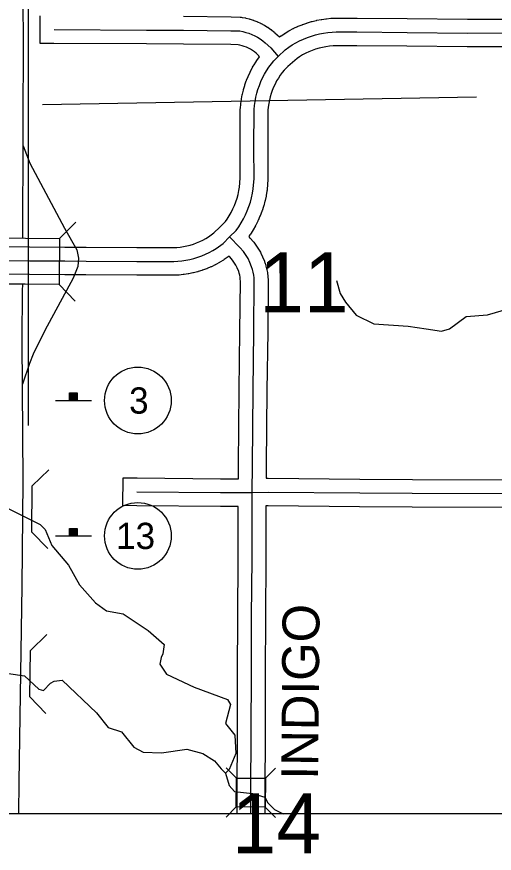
# Model space of a CAD drawing. Extents: x -2251611 to -2054719, y -2227156 to -2099355.
# Drawn here: x -2135345 to -2129880, y -2144765 to -2135199 of the extents above; entities that cross this region are included whole.
import ezdxf

# ---------------------------------------------------------------- set-up
doc = ezdxf.new("R2010")
doc.units = 0
for name, color, linetype in [('Default', 7, 'Continuous'), ('dsnTextFinalPlan', 7, 'Continuous'), ('dsnTextNote', 7, 'Continuous'), ('Level 35', 7, 'Continuous'), ('tdCoHydroRiver', 7, 'Continuous'), ('tdCoInt', 7, 'Continuous'), ('tdCoIntRamp', 7, 'Continuous'), ('tdCoSecRdTxt', 7, 'Continuous'), ('tdCoSecRteBand', 7, 'Continuous'), ('tdCoSectLinePart', 7, 'Continuous'), ('tdCoSectNmbr', 7, 'Continuous'), ('tdCoStrucDivPri', 7, 'Continuous'), ('tdCoStrucNonDivPri', 7, 'Continuous'), ('tdCoStrucSec', 7, 'Continuous'), ('tdCoSurfAsphalt', 7, 'Continuous'), ('tdCoSurfConc', 7, 'Continuous'), ('tdCoSurfEarth', 7, 'Continuous'), ('tdCoSurfGravel', 7, 'Continuous')]:
    doc.layers.add(name, color=color, linetype=linetype)

msp = doc.modelspace()

# ---------------------------------------------------------------- linework, layer by layer
at = {"layer": 'Default'}
msp.add_line((-2135211.4, -2139873.6), (-2135211.4, -2130143.9), dxfattribs=at)
at = {"layer": 'dsnTextFinalPlan'}
for p, q in [((-2134901.9, -2139587.8), (-2134489.4, -2139587.8)), ((-2134738.9, -2139507.9), (-2134655.1, -2139507.9)), ((-2134655.1, -2139512.7), (-2134738.9, -2139512.7)), ((-2134738.9, -2139516), (-2134655.1, -2139516)), ((-2134655.1, -2139520.8), (-2134738.9, -2139520.8)), ((-2134738.9, -2139524.2), (-2134655.1, -2139523.9)), ((-2134655.1, -2139530.4), (-2134738.9, -2139530.7)), ((-2134738.9, -2139533.7), (-2134655.1, -2139533.7)), ((-2134655.1, -2139540.2), (-2134738.9, -2139540.2)), ((-2134738.9, -2139545.8), (-2134655.1, -2139545.8)), ((-2134655.1, -2139550.6), (-2134738.9, -2139550.9)), ((-2134738.9, -2139554), (-2134655.1, -2139554)), ((-2134655.1, -2139557.9), (-2134738.9, -2139557.9)), ((-2134738.9, -2139563), (-2134655.1, -2139563)), ((-2134655.1, -2139566.1), (-2134738.9, -2139566.1)), ((-2134738.9, -2139569.5), (-2134655.1, -2139569.5)), ((-2134655.1, -2139573.4), (-2134738.9, -2139573.4)), ((-2134738.9, -2139577.3), (-2134655.1, -2139577.3)), ((-2134655.1, -2139581.6), (-2134738.9, -2139581.6)), ((-2134738.9, -2141056.2), (-2134655.1, -2141056.2)), ((-2134655.1, -2141061), (-2134738.9, -2141061)), ((-2134738.9, -2141064.4), (-2134655.1, -2141064.4)), ((-2134655.1, -2141069.2), (-2134738.9, -2141069.2)), ((-2134738.9, -2141072.5), (-2134655.1, -2141072.3)), ((-2134655.1, -2141078.7), (-2134738.9, -2141079)), ((-2134738.9, -2141082.1), (-2134655.1, -2141082.1)), ((-2134655.1, -2141088.6), (-2134738.9, -2141088.6)), ((-2134738.9, -2141094.2), (-2134655.1, -2141094.2)), ((-2134655.1, -2141099), (-2134738.9, -2141099.3)), ((-2134738.9, -2141102.4), (-2134655.1, -2141102.4)), ((-2134655.1, -2141106.3), (-2134738.9, -2141106.3)), ((-2134738.9, -2141111.4), (-2134655.1, -2141111.4)), ((-2134655.1, -2141114.4), (-2134738.9, -2141114.4)), ((-2134738.9, -2141117.8), (-2134655.1, -2141117.8)), ((-2134655.1, -2141121.8), (-2134738.9, -2141121.8)), ((-2134738.9, -2141125.7), (-2134655.1, -2141125.7)), ((-2134901.9, -2141136.1), (-2134489.4, -2141136.1)), ((-2134655.1, -2141129.9), (-2134738.9, -2141129.9))]:
    msp.add_line(p, q, dxfattribs=at)
for points in [[(-2134655.1, -2139586.3), (-2134739.5, -2139586.3), (-2134739.5, -2139502), (-2134655.1, -2139502)], [(-2134655.1, -2141134.7), (-2134739.5, -2141134.7), (-2134739.5, -2141050.3), (-2134655.1, -2141050.3)]]:
    msp.add_lwpolyline(points, close=True, dxfattribs=at)
at = {"layer": 'dsnTextNote'}
msp.add_lwpolyline([(-2138305.1, -2118109.7), (-2124095.9, -2118109.7), (-2124095.9, -2144315.9), (-2146959.9, -2144315.9), (-2146959.9, -2118109.7), (-2138305.1, -2118109.7)], dxfattribs=at)
for centre in [(-2133958.9, -2139587.8), (-2133958.9, -2141136.1)]:
    msp.add_circle(centre, 381.4, dxfattribs=at)
at = {"layer": 'Level 35'}
msp.add_lwpolyline([(-2136026.4, -2137722.3), (-2134855.8, -2137734.1), (-2134861.1, -2138261.9), (-2136033.1, -2138251.9)], close=True, dxfattribs=at)
at = {"layer": 'tdCoHydroRiver'}
for points in [[(-2131685.2, -2138213.7), (-2131643.2, -2138363.6), (-2131584.6, -2138463.5), (-2131459.3, -2138613.1), (-2131259.1, -2138712.7), (-2130867.4, -2138736.8), (-2130659, -2138769.6), (-2130483.9, -2138794.2), (-2130392.3, -2138769), (-2130201, -2138626.9), (-2129959.4, -2138609.7), (-2129709.6, -2138534.1)], [(-2135729.1, -2140681.2), (-2135078.4, -2141004.6), (-2135019.9, -2141062.8), (-2134944.5, -2141246), (-2134752.3, -2141470.5), (-2134626.8, -2141695.2), (-2134443, -2141903.1), (-2134317.8, -2141994.4), (-2134126, -2142027.3), (-2133842.3, -2142218.3), (-2133658.6, -2142376.2), (-2133675, -2142484.6), (-2133691.6, -2142526.3), (-2133708.1, -2142601.3), (-2133632.8, -2142717.8), (-2133315.8, -2142867), (-2132932.2, -2143007.8), (-2132898.7, -2143066), (-2132956.5, -2143282.8), (-2132847.9, -2143415.9), (-2132839.1, -2143624.2), (-2132913.6, -2143807.6), (-2132955.2, -2143849.4)], [(-2135807.8, -2142656.2), (-2135257.6, -2142738.2), (-2135090.6, -2142887.8), (-2135040.6, -2142904.3), (-2134957.4, -2142820.8), (-2134915.8, -2142795.7), (-2134824.2, -2142787.2), (-2134431.7, -2143161.2), (-2134298, -2143327.6), (-2134147.9, -2143377.2), (-2134005.8, -2143551.9), (-2133897.4, -2143610), (-2133689, -2143617.8), (-2133397.5, -2143575.5), (-2133214, -2143625.1), (-2133080.5, -2143708.1), (-2133005.3, -2143799.5), (-2132955.2, -2143849.4)], [(-2132955.2, -2143849.4), (-2132913.2, -2143991), (-2132854.7, -2144057.5), (-2132646.4, -2144082), (-2132504.6, -2144123.4), (-2132471.1, -2144189.9), (-2132396, -2144264.8), (-2132296, -2144315.9)]]:
    msp.add_lwpolyline(points, dxfattribs=at)
at = {"layer": 'tdCoInt'}
for points in [[(-2135275.9, -2137726.7), (-2135266.4, -2135362.5), (-2135283.2, -2134507.8), (-2135280.8, -2130380.1), (-2135260.2, -2129703.7), (-2135216.9, -2129339.5), (-2135162.2, -2129034.2), (-2135027.4, -2128516.2), (-2134871.9, -2128070.7), (-2134130.5, -2126105.6), (-2133742.1, -2125075.1), (-2133739, -2125066.2)], [(-2135322.6, -2144315.9), (-2135318.4, -2143949.7), (-2135284.3, -2141709.3), (-2135271.9, -2140509.2), (-2135282.8, -2138906), (-2135277.3, -2138327.8)], [(-2135277.4, -2138329.8), (-2135275.9, -2138261.1)]]:
    msp.add_lwpolyline(points, dxfattribs=at)
at = {"layer": 'tdCoIntRamp'}
msp.add_lwpolyline([(-2135271.7, -2136677.3), (-2135194, -2136874.8), (-2134798.4, -2137617), (-2134656.8, -2137864.4), (-2134637.7, -2137959), (-2134645.3, -2138055.3), (-2134697.5, -2138188.3), (-2135024.7, -2138788.9), (-2135156.5, -2139059.1), (-2135200.5, -2139166.5), (-2135279.4, -2139400.4)], dxfattribs=at)
at = {"layer": 'tdCoSecRteBand'}
for points in [[(-2133970.4, -2137839.2), (-2133551.9, -2137839.2), (-2133513.2, -2137837.2), (-2133474.4, -2137833.3), (-2133435.9, -2137827.4), (-2133397.8, -2137819.7), (-2133360.1, -2137810.1), (-2133322.8, -2137798.6), (-2133286.3, -2137785.3), (-2133250.4, -2137770.2), (-2133215.3, -2137753.4), (-2133181, -2137734.8), (-2133149.7, -2137715.8), (-2133089.2, -2137672.1), (-2133020.3, -2137604.9), (-2132956.9, -2137542), (-2132937, -2137513.8), (-2132913.1, -2137476.2), (-2132891.2, -2137437.5), (-2132871.2, -2137397.7), (-2132853.2, -2137357), (-2132837.2, -2137315.5), (-2132823.3, -2137273.2), (-2132811.5, -2137230.2), (-2132801.9, -2137186.8), (-2132795.1, -2137146.9), (-2132788.2, -2137044.6), (-2132789.5, -2136700), (-2132789.5, -2136699.2), (-2132789.5, -2136698.5), (-2132786.9, -2136259.7), (-2132786.9, -2136252.8), (-2132786.2, -2136246), (-2132781.9, -2136199), (-2132781.5, -2136195.2), (-2132781, -2136191.4), (-2132774.4, -2136144.7), (-2132773.8, -2136140.9), (-2132773.1, -2136137.1), (-2132764.2, -2136090.8), (-2132763.4, -2136087), (-2132762.5, -2136083.2), (-2132751.4, -2136037.4), (-2132750.5, -2136033.6), (-2132749.4, -2136029.9), (-2132736, -2135984.7), (-2132734.9, -2135981), (-2132733.6, -2135977.4), (-2132718, -2135932.9), (-2132716.8, -2135929.2), (-2132715.3, -2135925.6), (-2132697.6, -2135881.9), (-2132696.1, -2135878.3), (-2132694.5, -2135874.8), (-2132674.7, -2135832.1), (-2132673, -2135828.6), (-2132671.2, -2135825.1), (-2132649.3, -2135783.4), (-2132647.6, -2135779.9), (-2132645.6, -2135776.6), (-2132621.7, -2135736), (-2132619.7, -2135732.6), (-2132617.6, -2135729.4), (-2132591.7, -2135690), (-2132589.6, -2135686.7), (-2132587.3, -2135683.6), (-2132568, -2135657), (-2132575.6, -2135649.1), (-2132572.7, -2135646.4), (-2132604.8, -2135615.7), (-2132623.7, -2135600.7), (-2132645.5, -2135585.4), (-2132668.2, -2135571.4), (-2132691.7, -2135558.9), (-2132715.9, -2135547.8), (-2132740.8, -2135538.2), (-2132766.2, -2135530.1), (-2132792, -2135523.6), (-2132810.3, -2135520.1), (-2132896.7, -2135517.9), (-2133437.9, -2135511.4), (-2133859, -2135510.1), (-2133859.2, -2135510.1), (-2133859.3, -2135510.1), (-2134919.2, -2135504.9), (-2135077.6, -2135504.1), (-2135076.1, -2135187.3)], [(-2133434.8, -2135194.6), (-2132891.8, -2135201.1), (-2132890.7, -2135201.2), (-2132889.6, -2135201.2), (-2132789.3, -2135203.8), (-2132776.6, -2135204.1), (-2132764, -2135206.5), (-2132728.4, -2135213.2), (-2132723.7, -2135214.1), (-2132719, -2135215.3), (-2132683.9, -2135224.2), (-2132679.2, -2135225.3), (-2132674.7, -2135226.8), (-2132640.1, -2135237.8), (-2132635.6, -2135239.3), (-2132631.1, -2135241), (-2132597.3, -2135254), (-2132592.8, -2135255.8), (-2132588.4, -2135257.8), (-2132555.5, -2135272.9), (-2132551.1, -2135274.9), (-2132546.9, -2135277.1), (-2132514.9, -2135294.2), (-2132510.7, -2135296.4), (-2132506.6, -2135298.9), (-2132475.7, -2135317.9), (-2132471.6, -2135320.4), (-2132467.6, -2135323.2), (-2132438, -2135344), (-2132434, -2135346.7), (-2132430.3, -2135349.7), (-2132401.9, -2135372.3), (-2132396.2, -2135376.8), (-2132390.9, -2135381.9), (-2132339.9, -2135430.8), (-2132325.6, -2135420.4), (-2132322.5, -2135418.2), (-2132319.3, -2135416.1), (-2132278.9, -2135389.6), (-2132275.6, -2135387.5), (-2132272.3, -2135385.6), (-2132230.7, -2135361.1), (-2132227.3, -2135359.2), (-2132224, -2135357.4), (-2132181.1, -2135335), (-2132177.7, -2135333.2), (-2132174.2, -2135331.6), (-2132130.4, -2135311.3), (-2132126.9, -2135309.7), (-2132123.4, -2135308.2), (-2132078.6, -2135290), (-2132075, -2135288.6), (-2132071.4, -2135287.3), (-2132025.8, -2135271.3), (-2132022.2, -2135270.1), (-2132018.5, -2135269), (-2131972.1, -2135255.2), (-2131968.5, -2135254.1), (-2131964.7, -2135253.2), (-2131917.8, -2135241.7), (-2131914.1, -2135240.8), (-2131910.3, -2135240.1), (-2131862.9, -2135230.9), (-2131859.1, -2135230.1), (-2131855.3, -2135229.6), (-2131807.5, -2135222.7), (-2131803.7, -2135222.1), (-2131799.8, -2135221.8), (-2131751.7, -2135217.2), (-2131747.9, -2135216.8), (-2131744.1, -2135216.6), (-2131695.8, -2135214.4), (-2131692.1, -2135214.2), (-2131688.4, -2135214.2), (-2131451.4, -2135214.2), (-2131450.7, -2135214.2), (-2131450, -2135214.2), (-2130877.1, -2135219.4), (-2130876.9, -2135219.4), (-2130876.7, -2135219.4), (-2130187.6, -2135227.2), (-2129049.3, -2135225.9)], [(-2129049.3, -2135542.7), (-2130188.2, -2135544), (-2130189.2, -2135544), (-2130190.2, -2135544), (-2130880.1, -2135536.2), (-2131452.2, -2135531), (-2131684.7, -2135531), (-2131725.5, -2135532.9), (-2131766, -2135536.8), (-2131806.2, -2135542.6), (-2131846.1, -2135550.3), (-2131885.6, -2135560), (-2131924.6, -2135571.6), (-2131963, -2135585), (-2132000.7, -2135600.3), (-2132037.6, -2135617.4), (-2132073.6, -2135636.3), (-2132108.7, -2135656.9), (-2132137.7, -2135675.9), (-2132244.2, -2135770.1), (-2132285, -2135809.3), (-2132305.8, -2135835.1), (-2132329, -2135867), (-2132350.6, -2135899.9), (-2132370.6, -2135933.9), (-2132388.9, -2135968.8), (-2132405.5, -2136004.6), (-2132420.3, -2136041.1), (-2132433.3, -2136078.3), (-2132444.5, -2136116.1), (-2132453.8, -2136154.4), (-2132461.3, -2136193.1), (-2132466.8, -2136232.1), (-2132470.2, -2136268.4), (-2132472.7, -2136699.6), (-2132471.4, -2137049.1), (-2132471.4, -2137054.7), (-2132471.8, -2137060.3), (-2132479.6, -2137176.2), (-2132480.1, -2137184.2), (-2132481.5, -2137192.1), (-2132490.2, -2137243.7), (-2132490.9, -2137247.6), (-2132491.8, -2137251.5), (-2132503.1, -2137302.6), (-2132503.9, -2137306.4), (-2132505, -2137310.2), (-2132518.8, -2137360.7), (-2132519.9, -2137364.5), (-2132521.1, -2137368.3), (-2132537.4, -2137418), (-2132538.7, -2137421.8), (-2132540.1, -2137425.4), (-2132558.8, -2137474.3), (-2132560.3, -2137478), (-2132561.8, -2137481.6), (-2132583, -2137529.5), (-2132584.6, -2137533.1), (-2132586.4, -2137536.6), (-2132609.9, -2137583.4), (-2132611.7, -2137586.9), (-2132613.6, -2137590.3), (-2132639.5, -2137635.9), (-2132641.4, -2137639.3), (-2132643.5, -2137642.6), (-2132671.6, -2137686.8), (-2132673.7, -2137690.1), (-2132676, -2137693.4), (-2132690.3, -2137713.7), (-2132685.2, -2137718.8), (-2132686.1, -2137719.6), (-2132680, -2137725.9), (-2132678.3, -2137727.6), (-2132676.7, -2137729.4), (-2132632.4, -2137777.5), (-2132623.2, -2137787.5), (-2132615.9, -2137798.9), (-2132563.8, -2137879.6), (-2132556.9, -2137890.3), (-2132551.8, -2137902.1), (-2132532.8, -2137945.5), (-2132511.4, -2137994.5), (-2132508, -2138002.3), (-2132505.5, -2138010.4), (-2132495.7, -2138041.6), (-2132494.2, -2138046.1), (-2132493.1, -2138050.7), (-2132485.2, -2138082.4), (-2132484, -2138087), (-2132483.1, -2138091.7), (-2132477.1, -2138123.9), (-2132476.2, -2138128.5), (-2132475.6, -2138133.2), (-2132471.6, -2138165.7), (-2132471, -2138170.4), (-2132470.7, -2138175.1), (-2132468.6, -2138207.8), (-2132468.2, -2138213.6), (-2132468.2, -2138219.5), (-2132473.4, -2138801.5), (-2132473.4, -2138801.9), (-2132473.4, -2138802.2), (-2132482.6, -2139473.6), (-2132489.1, -2140324.7), (-2132489.1, -2140324.8), (-2132489.1, -2140324.8), (-2132490.3, -2140477), (-2132471.9, -2140476.6), (-2132469.4, -2140476.5), (-2132466.9, -2140476.5), (-2131418.9, -2140485.7), (-2130817.6, -2140489.6), (-2129765.6, -2140494.8)], [(-2135855.2, -2137824.3), (-2135197.4, -2137830.8), (-2134792.8, -2137833.2), (-2134792.6, -2137833.3), (-2134792.5, -2137833.3), (-2134550.6, -2137834.7), (-2134550.4, -2137834.7), (-2134550.3, -2137834.7), (-2133970.4, -2137839.2)], [(-2132823.7, -2144315.9), (-2132822.8, -2144085.9), (-2132822.8, -2144085.8), (-2132822.8, -2144085.7), (-2132818.9, -2143371.1), (-2132817.6, -2142713.8), (-2132817.6, -2142713.7), (-2132817.6, -2142713.5), (-2132815, -2142054.7), (-2132815, -2142054.3), (-2132815, -2142054), (-2132809.8, -2141401), (-2132809.8, -2140799.5), (-2133013.3, -2140798.5), (-2133013.6, -2140798.5), (-2133013.8, -2140798.5), (-2133970.8, -2140790.7), (-2134129.2, -2140789.4), (-2134126.6, -2140472.6), (-2133968.3, -2140473.9), (-2133011.5, -2140481.7), (-2132807.2, -2140482.8), (-2132807.1, -2140479.4), (-2132805.8, -2140322.3), (-2132799.3, -2139470.7), (-2132799.3, -2139470.3), (-2132799.3, -2139469.8), (-2132790.2, -2138798.3), (-2132785.1, -2138222.5), (-2132786.5, -2138200.4), (-2132789.4, -2138177.4), (-2132793.7, -2138154.6), (-2132799.3, -2138132.1), (-2132805.1, -2138113.5), (-2132823.1, -2138072.3), (-2132837, -2138040.6), (-2132874.8, -2137982), (-2132908.3, -2137945.5), (-2132915.9, -2137937.7), (-2132969.4, -2137976.3), (-2132974.5, -2137980), (-2132979.8, -2137983.2), (-2133019.8, -2138007.5), (-2133023.1, -2138009.5), (-2133026.5, -2138011.4), (-2133067.7, -2138033.7), (-2133071.1, -2138035.6), (-2133074.6, -2138037.3), (-2133116.8, -2138057.5), (-2133120.3, -2138059.2), (-2133124, -2138060.7), (-2133167.1, -2138078.9), (-2133170.7, -2138080.4), (-2133174.4, -2138081.7), (-2133218.3, -2138097.7), (-2133222, -2138099), (-2133225.8, -2138100.2), (-2133270.5, -2138114), (-2133274.2, -2138115.1), (-2133278, -2138116.1), (-2133323.3, -2138127.6), (-2133327.1, -2138128.6), (-2133331, -2138129.4), (-2133376.8, -2138138.7), (-2133380.7, -2138139.5), (-2133384.5, -2138140.1), (-2133430.8, -2138147.1), (-2133434.7, -2138147.7), (-2133438.6, -2138148.1), (-2133485.1, -2138152.8), (-2133489, -2138153.2), (-2133492.9, -2138153.4), (-2133539.6, -2138155.8), (-2133543.7, -2138156), (-2133547.8, -2138156), (-2133971, -2138156), (-2133971.6, -2138156), (-2133972.2, -2138156), (-2134552.6, -2138151.5), (-2134794.6, -2138150), (-2134794.9, -2138150), (-2134795, -2138150), (-2135199.6, -2138147.6), (-2135199.9, -2138147.6), (-2135200.2, -2138147.6), (-2135859.1, -2138141.1)], [(-2129767.7, -2140811.6), (-2130819.3, -2140806.3), (-2130819.4, -2140806.3), (-2130819.5, -2140806.3), (-2131421.1, -2140802.4), (-2131421.3, -2140802.4), (-2131421.4, -2140802.4), (-2132467.1, -2140793.3), (-2132488.1, -2140793.8), (-2132492.9, -2140793.9), (-2132493, -2140796.8), (-2132493, -2141401.6), (-2132493, -2141402.3), (-2132493, -2141402.9), (-2132498.2, -2142056.2), (-2132500.8, -2142714.6), (-2132502.1, -2143372), (-2132502.1, -2143372.3), (-2132502.1, -2143372.6), (-2132506, -2144087.3), (-2132506.9, -2144315.9)]]:
    msp.add_lwpolyline(points, dxfattribs=at)
at = {"layer": 'tdCoSectLinePart'}
msp.add_lwpolyline([(-2135051.4, -2136202.8), (-2130082.7, -2136117.1)], dxfattribs=at)
at = {"layer": 'tdCoStrucDivPri'}
for points in [[(-2134987.6, -2141281.1), (-2135172.3, -2141092.5), (-2135166.8, -2140564.5), (-2134978.2, -2140379.8)], [(-2135013.4, -2143166.1), (-2135197, -2142976.4), (-2135188.4, -2142448.5), (-2134998.8, -2142264.9)]]:
    msp.add_lwpolyline(points, dxfattribs=at)
at = {"layer": 'tdCoStrucNonDivPri'}
for p, q in [((-2134855.9, -2137733.9), (-2134667.3, -2137549.1)), ((-2134861.1, -2138261.9), (-2134676.2, -2138450.4))]:
    msp.add_line(p, q, dxfattribs=at)
msp.add_lwpolyline([(-2136026.4, -2137722.3), (-2134855.9, -2137733.9), (-2134861.1, -2138261.9), (-2136031.6, -2138250.3)], close=True, dxfattribs=at)
at = {"layer": 'tdCoStrucSec'}
for p, q in [((-2132830.5, -2143905.8), (-2132946.7, -2143788.3)), ((-2132499.9, -2143907.6), (-2132382.4, -2143791.4)), ((-2132832.3, -2144236.3), (-2132949.8, -2144352.5)), ((-2132501.7, -2144238.1), (-2132385.5, -2144355.6))]:
    msp.add_line(p, q, dxfattribs=at)
msp.add_lwpolyline([(-2132832.3, -2144236.3), (-2132830.5, -2143905.8), (-2132499.9, -2143907.6), (-2132501.7, -2144238.1)], close=True, dxfattribs=at)
at = {"layer": 'tdCoSurfAsphalt'}
for points in [[(-2132351.6, -2135653.7), (-2132271.7, -2135577), (-2132232.6, -2135548.6), (-2132192.2, -2135522.2), (-2132150.5, -2135497.7), (-2132107.7, -2135475.3), (-2132063.8, -2135455), (-2132019, -2135436.8), (-2131973.4, -2135420.8), (-2131927.1, -2135407.1), (-2131880.1, -2135395.6), (-2131832.7, -2135386.3), (-2131784.8, -2135379.4), (-2131736.7, -2135374.9), (-2131688.4, -2135372.6), (-2131451.4, -2135372.6), (-2130878.5, -2135377.8), (-2130188.4, -2135385.6), (-2129049.1, -2135384.3), (-2128013.9, -2135388.2), (-2127452.7, -2135386.9), (-2127364, -2135386.5)], [(-2132909.2, -2137717.8), (-2132835.5, -2137644.7), (-2132805.3, -2137602), (-2132777.3, -2137557.7), (-2132751.4, -2137512.2), (-2132727.9, -2137465.4), (-2132706.7, -2137417.5), (-2132687.9, -2137368.6), (-2132671.6, -2137318.8), (-2132657.7, -2137268.3), (-2132646.4, -2137217.2), (-2132637.6, -2137165.6), (-2132629.8, -2137049.7), (-2132631.1, -2136699.4), (-2132628.5, -2136260.6), (-2132624.2, -2136213.7), (-2132617.5, -2136167), (-2132608.6, -2136120.7), (-2132597.5, -2136074.9), (-2132584.1, -2136029.7), (-2132568.5, -2135985.2), (-2132550.8, -2135941.5), (-2132531, -2135898.7), (-2132509.1, -2135856.9), (-2132485.2, -2135816.3), (-2132459.3, -2135776.9), (-2132431.5, -2135738.7), (-2132402, -2135702), (-2132351.6, -2135653.7)], [(-2134793.7, -2137991.6), (-2134551.5, -2137993.1), (-2133971, -2137997.6), (-2133547.8, -2137997.6), (-2133501.1, -2137995.2), (-2133454.5, -2137990.5), (-2133408.3, -2137983.4), (-2133362.5, -2137974.1), (-2133317.1, -2137962.6), (-2133272.4, -2137948.8), (-2133228.5, -2137932.8), (-2133185.4, -2137914.7), (-2133143.2, -2137894.5), (-2133102.1, -2137872.2), (-2133062.1, -2137847.9), (-2132982.7, -2137790.6), (-2132909.2, -2137717.8)]]:
    msp.add_lwpolyline(points, dxfattribs=at)
at = {"layer": 'tdCoSurfConc'}
msp.add_lwpolyline([(-2137923.4, -2137962.1), (-2137787.4, -2137963.7), (-2136881.1, -2137969), (-2136338, -2137973.6), (-2136083.4, -2137978.4), (-2135857.5, -2137982.7), (-2135198.7, -2137989.2), (-2134793.8, -2137991.6), (-2134793.7, -2137991.6)], dxfattribs=at)
at = {"layer": 'tdCoSurfEarth'}
msp.add_lwpolyline([(-2133969.5, -2140632.3), (-2133012.5, -2140640.1), (-2132750.8, -2140641.4), (-2132650.1, -2140639.1)], dxfattribs=at)
at = {"layer": 'tdCoSurfGravel'}
for points in [[(-2134918.4, -2135346.5), (-2133858.6, -2135351.7), (-2133436.7, -2135353), (-2132893.7, -2135359.5), (-2132793.4, -2135362.1), (-2132757.8, -2135368.9), (-2132722.7, -2135377.7), (-2132688.2, -2135388.7), (-2132654.4, -2135401.8), (-2132621.4, -2135416.9), (-2132589.4, -2135433.9), (-2132558.5, -2135452.9), (-2132528.9, -2135473.7), (-2132500.5, -2135496.2), (-2132438, -2135556.1), (-2132351.6, -2135653.7)], [(-2132678, -2138008.9), (-2132696.9, -2137965.5), (-2132749, -2137884.7), (-2132793.3, -2137836.5), (-2132909.2, -2137717.8)], [(-2132665.3, -2144315.9), (-2132664.4, -2144086.5), (-2132660.5, -2143371.7), (-2132659.2, -2142714.1), (-2132656.6, -2142055.3), (-2132651.4, -2141401.6), (-2132651.4, -2140796.2), (-2132650.1, -2140639.1), (-2132647.5, -2140323.5), (-2132640.9, -2139472), (-2132631.8, -2138800.1), (-2132626.6, -2138218.1), (-2132628.7, -2138185.4), (-2132632.8, -2138153), (-2132638.8, -2138120.8), (-2132646.8, -2138089.1), (-2132656.6, -2138057.9), (-2132678, -2138008.9)], [(-2132650.1, -2140639.1), (-2132468.2, -2140634.9), (-2131420.1, -2140644), (-2130818.5, -2140648), (-2129766.4, -2140653.2), (-2129076.3, -2140661), (-2128280.8, -2140666.2), (-2127621.9, -2140670.1), (-2127483.9, -2140667.5), (-2127388.7, -2140666.5), (-2127228.7, -2140664.9), (-2126592, -2140663.6), (-2125655.8, -2140654.5), (-2124637.5, -2140644), (-2124095.9, -2140640.8)]]:
    msp.add_lwpolyline(points, dxfattribs=at)

# ---------------------------------------------------------------- texts
at = {"layer": 'dsnTextNote'}
for s, p in [('3', (-2134059.2, -2139737.8)), ('13', (-2134208, -2141286.1))]:
    msp.add_text(s, height=300, dxfattribs=at).set_placement(p)
at = {"layer": 'tdCoSecRdTxt'}
msp.add_text('INDIGO', height=422.4, rotation=89.49741, dxfattribs=at).set_placement((-2131896.8, -2143924.9))
at = {"layer": 'tdCoSectNmbr'}
for s, rotation, p in [('11', 0.01995, (-2132568.7, -2138580.9)), ('14', 0.01981, (-2132884.4, -2144765.5))]:
    msp.add_text(s, height=686.4, rotation=rotation, dxfattribs=at).set_placement(p)

doc.saveas('drawing.dxf')
